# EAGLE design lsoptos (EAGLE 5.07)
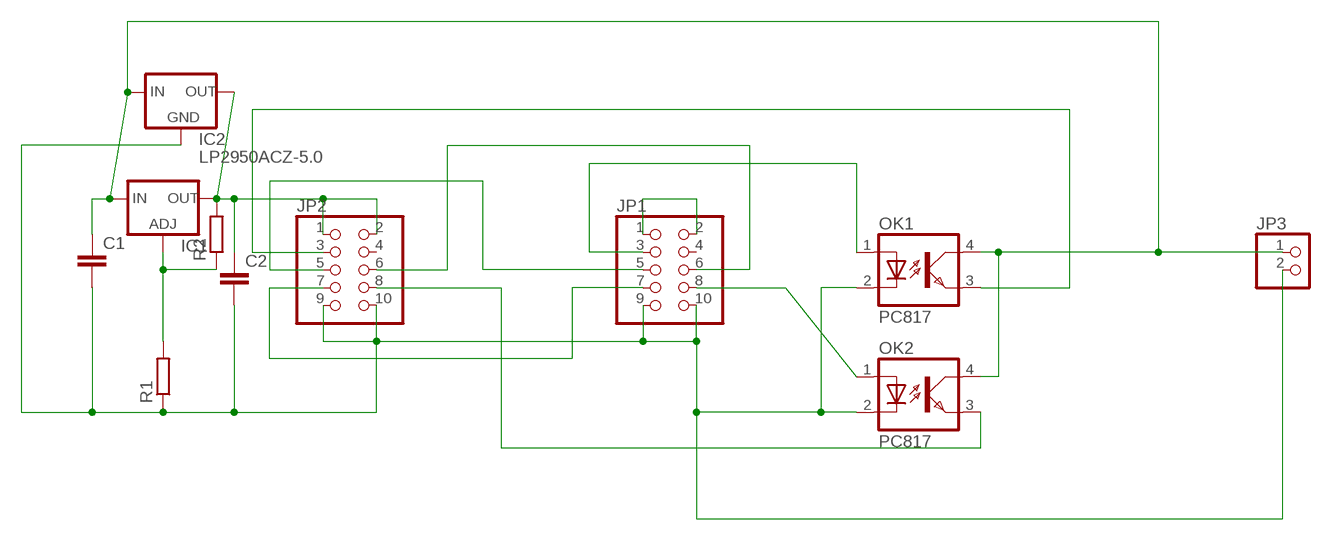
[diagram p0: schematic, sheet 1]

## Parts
C1  C-EUC1206  [C1206]
C2  C-EUC1206  [C1206]
IC1  LM317LM-OUTPIN7  [SO08]
IC2  LP2950ACZ-5.0  [TO92]
JP1  PINHD-2X5  [2X05]
JP2  PINHD-2X5  [2X05]
JP3  PINHD-1X2STR  [1X02]
OK1  PC817  [DIL04]
OK2  PC817  [DIL04]
R1  R-EU_R0805  [R0805]
R2  R-EU_R0805  [R0805]

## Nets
GND: C1.2 C2.2 IC2.2(GND) JP1.9 JP1.10 JP2.9 JP2.10 JP3.2 OK1.2(C) OK2.2(C) R1.1
N$1: JP1.3 OK1.1(A)
N$2: JP1.8 OK2.1(A)
N$3: JP2.8 OK2.3(EMIT)
N$4: JP2.3 OK1.3(EMIT)
N$6: C1.1 IC1.1(IN) IC2.3(IN) JP3.1 OK1.4(COL) OK2.4(COL)
N$7: JP1.5 JP2.5
N$8: JP1.6 JP2.6
N$9: JP1.7 JP2.7
N$11: JP1.1 JP1.2
N$14: IC1.4(ADJ) R1.2 R2.1
N$15: C2.1 IC1.7(OUT) IC2.1(OUT) JP2.1 JP2.2 R2.2
Unconnected: JP1.4 JP2.4

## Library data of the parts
C1 C2 = rcl:C-EU: CAPACITOR, European symbol
IC1 = v-reg-3:LM317L: Adjustable Voltage Regulator, 1.2V to 37V, 100mA
IC2 = v-reg:LP2950?*: Source: http://cache.national.com/ds/LP/LP2950.pdf
JP1 JP2 = pinhead:PINHD-2X5: PIN HEADER
JP3 = pinhead:PINHD-1X2: PIN HEADER
OK1 OK2 = optocoupler:PC817: SHARP OPTO COUPLER
R1 R2 = rcl:R-EU_: RESISTOR, European symbol

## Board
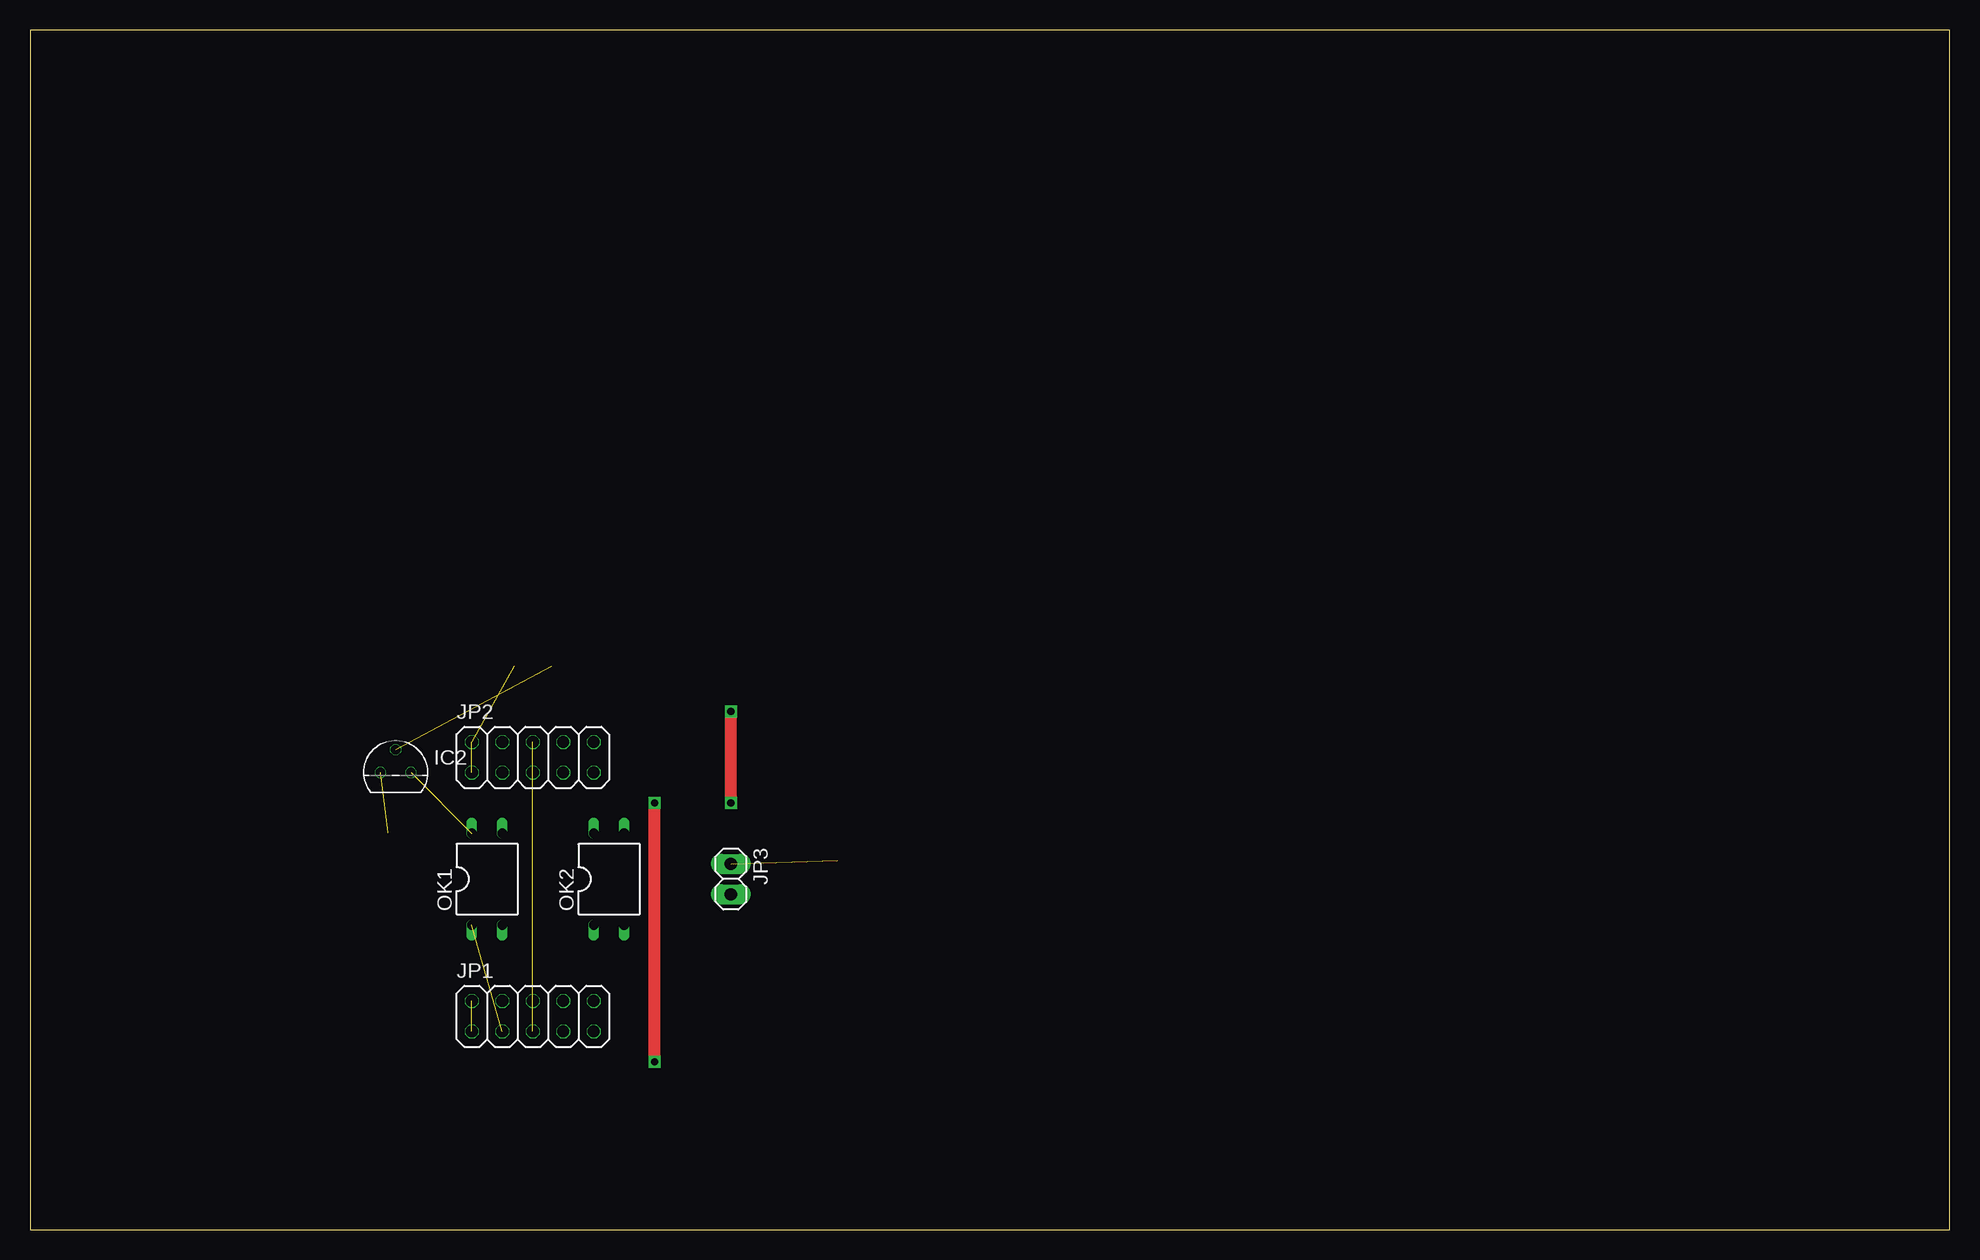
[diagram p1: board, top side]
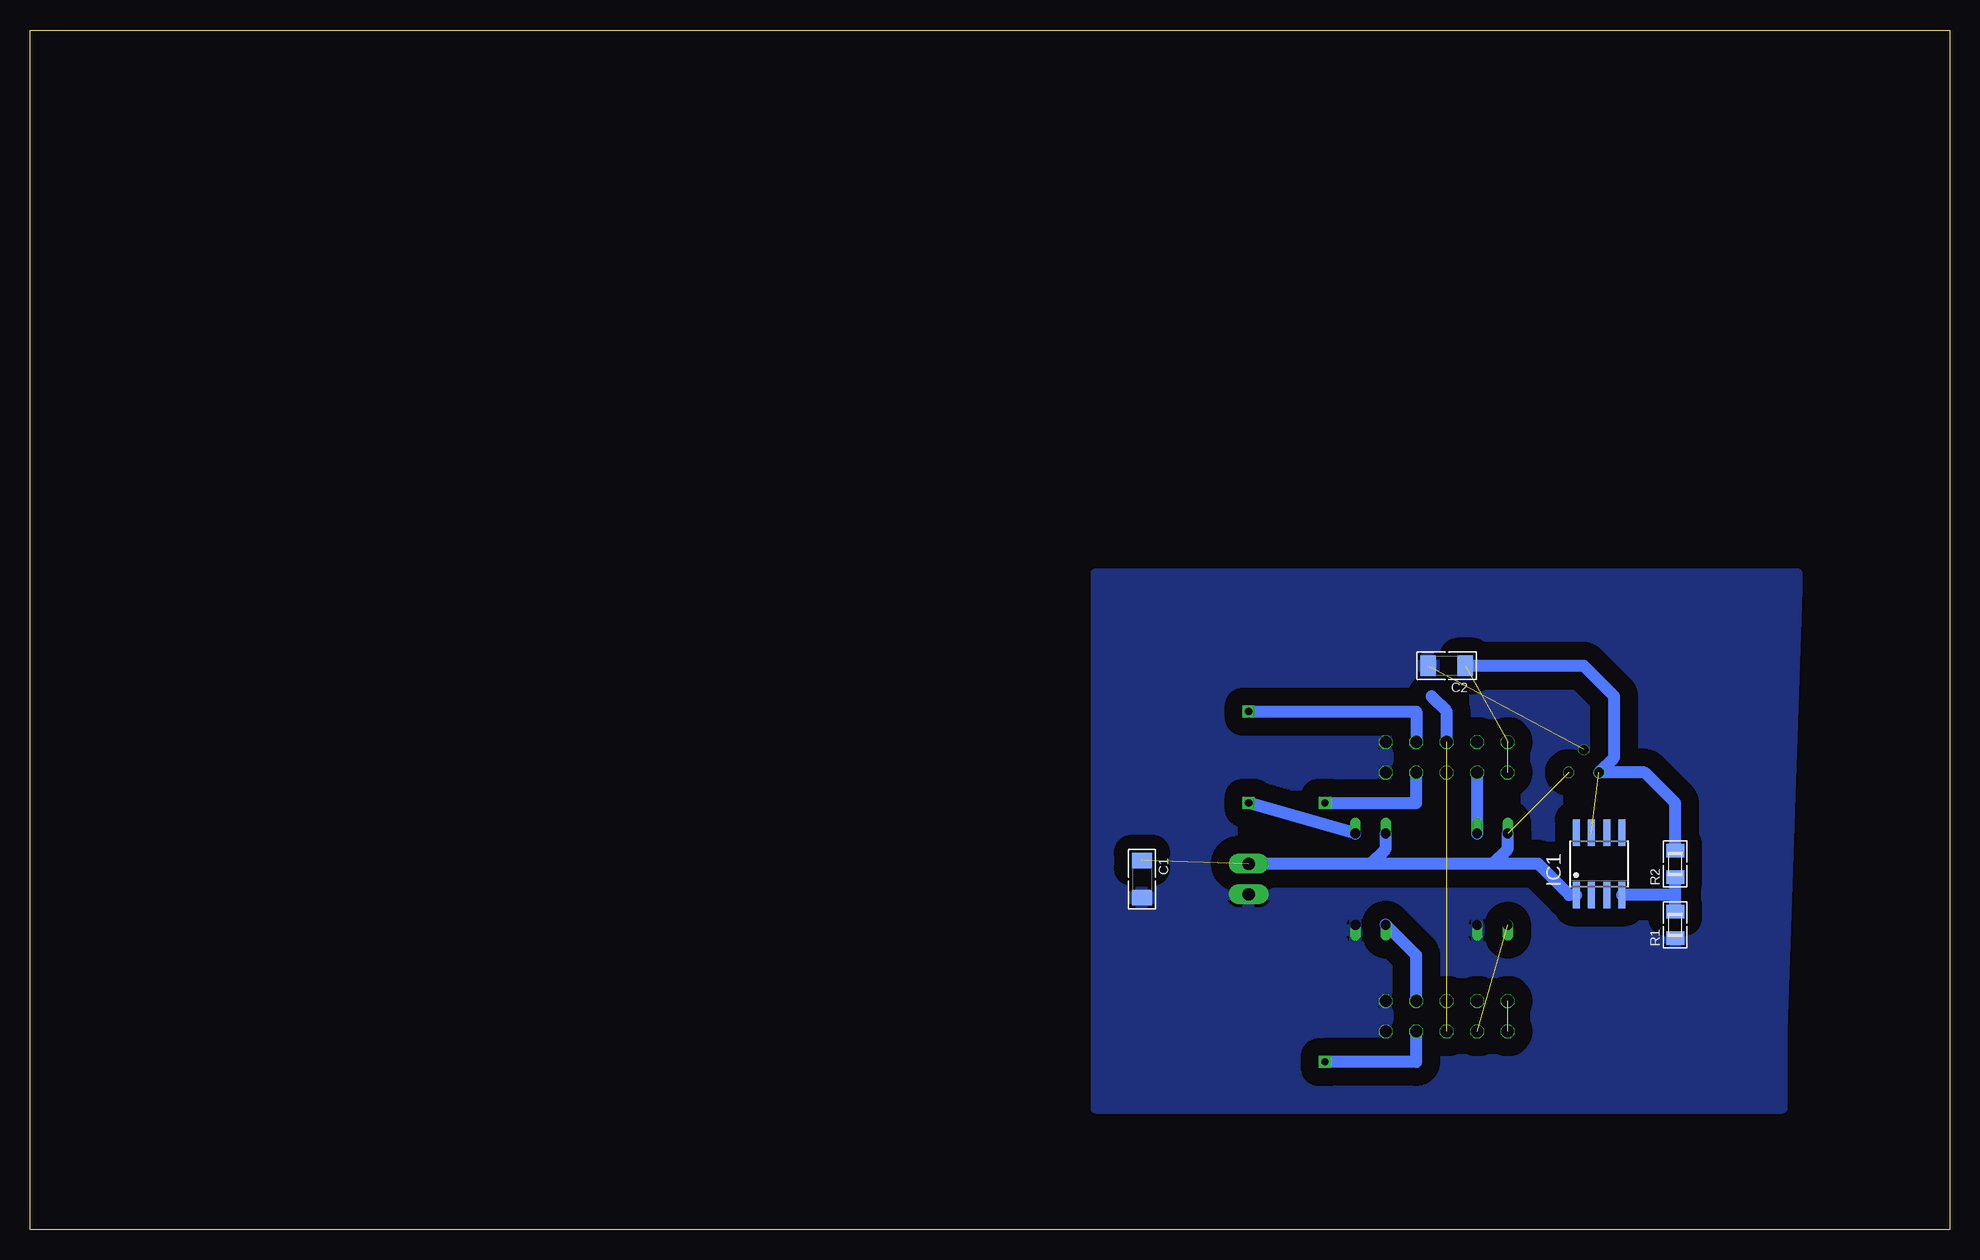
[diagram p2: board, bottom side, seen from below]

Size 160 x 100 mm. Coordinates in mm from the lower left corner, seen from the top.
Outline: 0,0 160,0 160,100 0,100 0,0
Copper layers (1*16): Top 0.035mm / dielectric 1.5mm / Bottom 0.035mm
Design rules "default": minimum track width 10mil, minimum drill 20mil, track to track 8mil, track to pad 8mil, pad to pad 8mil, via to via 8mil, smd to smd 8mil, copper to edge 40mil, drill to drill 8mil, minimum pad ring 1mil, minimum via ring 8mil, stop-mask expansion 4mil, vias tented up to drill 0mil, thermal gap 10mil

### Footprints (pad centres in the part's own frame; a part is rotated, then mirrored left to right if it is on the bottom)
C1206 = smd 1.3 x 1.7: 1 -1.55,0; 2 1.55,0
SO08 = smd 0.6 x 2.2: 1 -1.905,-2.6; 2 -0.635,-2.6; 3 0.635,-2.6; 4 1.905,-2.6; 5 1.905,2.6; 6 0.635,2.6; 7 -0.635,2.6; 8 -1.905,2.6
TO92 = drill 0.813 octagon: 1 -1.27,0; 2 0,1.905; 3 1.27,0
2X05 = drill 1.016 octagon: 1 -5.08,-1.27; 2 -5.08,1.27; 3 -2.54,-1.27; 4 -2.54,1.27; 5 0,-1.27; 6 0,1.27; 7 2.54,-1.27; 8 2.54,1.27; 9 5.08,-1.27; 10 5.08,1.27
1X02 = drill 1.016 pad 1.676 long: 1 -1.27,0; 2 1.27,0
DIL04 = drill 0.813 offset: 1 -1.27,-3.81; 2 1.27,-3.81; 3 1.27,3.81; 4 -1.27,3.81
R0805 = smd 1.1 x 1.5: 1 -1.1,0; 2 1.1,0

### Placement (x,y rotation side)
C1  67.31,29.21 270 bottom
C2  41.91,46.99 180 bottom
IC1  29.21,30.48 0 bottom
IC2  30.48,38.1 0 top
JP1  41.91,17.78 0 top
JP2  41.91,39.37 0 top
JP3  58.42,29.21 270 top
OK1  38.1,29.21 0 top
OK2  48.26,29.21 0 top
R1  22.86,25.4 90 bottom
R2  22.86,30.48 90 bottom

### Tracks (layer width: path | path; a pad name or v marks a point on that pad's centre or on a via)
GND  (1 unrouted)
  pour Bottom (isolate 1.5): 12.7,54.61 71.12,54.61 71.12,10.16 13.97,10.16 13.97,16.51
N$1  (1 unrouted)
N$2
  Bottom 1: JP1.8 44.45,22.86 OK2.1
N$3  (via drill 0.6)
  Top 1: v58.42,35.56 v58.42,43.18
  Bottom 1: OK2.3 v58.42,35.56 | v58.42,43.18 44.45,43.18 JP2.8
N$4
  Bottom 1: OK1.3 JP2.3
N$6  (2 unrouted)
  Bottom 1: 48.26,30.48 JP3.1 | 48.26,30.48 46.99,31.75 OK2.4 | OK1.4 36.83,31.75 38.1,30.48 | 38.1,30.48 48.26,30.48 | IC1.1 31.69,27.88 34.29,30.48 38.1,30.48
N$7  (1 unrouted)
N$8  (1 unrouted)
  Bottom 1: JP2.6 41.91,43.18 43.18,44.45
N$9  (via drill 0.6)
  Top 1: v52.07,13.97 v52.07,35.56
  Bottom 1: JP2.7 44.45,35.56 v52.07,35.56 | v52.07,13.97 44.45,13.97 JP1.7
N$11  (1 unrouted)
N$14
  Bottom 1: R1.2 22.86,27.94 | 22.86,27.94 R2.1 | IC1.4 22.92,27.88 22.86,27.94
N$15  (3 unrouted)
  Bottom 1: C2.1 30.48,46.99 27.94,44.45 27.94,39.37 IC2.1 25.4,38.1 22.86,35.56 R2.2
